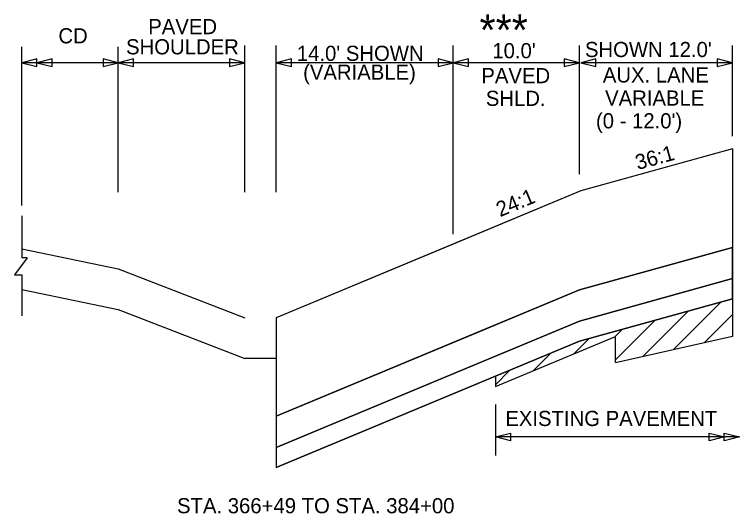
# Model space of a CAD drawing. Extents: x 4832 to 5477, y 4935 to 5220.
# Drawn here: x 4832.5 to 4889.8, y 5046 to 5085.4 of the extents above; entities that cross this region are included whole.
import ezdxf

# ---------------------------------------------------------------- set-up
doc = ezdxf.new("R2010")
doc.units = 0
for name, color, linetype in [('CLS_Clear_Zone', 7, 'Continuous'), ('Level 2', 7, 'Continuous'), ('RD_QTY_Milling', 7, 'Continuous'), ('RD_QTY_Miscl_1', 7, 'Continuous'), ('RD_QTY_Surf_Course', 7, 'Continuous'), ('RD_SHT_Typical', 7, 'Continuous'), ('RD_TX_TypSect', 7, 'Continuous'), ('RD_XS_ExPaveRet', 7, 'Continuous'), ('RD_XS_PaveShd', 7, 'Continuous'), ('TERMINATOR', 7, 'Continuous')]:
    doc.layers.add(name, color=color, linetype=linetype)

# ---------------------------------------------------------------- blocks, each defined once
blk = doc.blocks.new('AH')
at = {"layer": 'TERMINATOR'}
blk.add_lwpolyline([(-6, 1.5), (0, 0), (-6, -1.5)], close=True, dxfattribs=at)

msp = doc.modelspace()

# ---------------------------------------------------------------- linework, layer by layer
at = {"layer": 'CLS_Clear_Zone'}
msp.add_line((4853.19, 5053.657), (4853.19, 5049.59), dxfattribs=at)
at = {"layer": 'Level 2'}
msp.add_line((4853.188, 5058.235), (4850.689, 5058.235), dxfattribs=at)
at = {"layer": 'RD_QTY_Milling'}
for p, q in [((4889.27, 5067.011), (4889.27, 5067.011)), ((4889.27, 5067.011), (4889.27, 5067.011)), ((4889.27, 5064.542), (4889.27, 5067.011)), ((4853.19, 5053.657), (4853.19, 5051.188))]:
    msp.add_line(p, q, dxfattribs=at)
for points in [[(4889.27, 5067.011), (4877.179, 5063.653), (4853.19, 5053.657)], [(4853.19, 5051.188), (4877.179, 5061.183), (4889.27, 5064.542)]]:
    msp.add_lwpolyline(points, dxfattribs=at)
at = {"layer": 'RD_QTY_Miscl_1'}
for p, q in [((4889.27, 5064.542), (4877.179, 5061.183)), ((4889.275, 5062.946), (4889.27, 5064.542)), ((4889.27, 5064.542), (4889.27, 5064.542)), ((4877.179, 5059.586), (4889.275, 5062.946)), ((4877.179, 5059.586), (4877.179, 5059.586))]:
    msp.add_line(p, q, dxfattribs=at)
msp.add_lwpolyline([(4877.179, 5061.183), (4853.19, 5051.188), (4853.19, 5049.59), (4877.179, 5059.586)], dxfattribs=at)
at = {"layer": 'RD_QTY_Surf_Course'}
msp.add_line((4833.053, 5066.907), (4840.693, 5065.32), dxfattribs=at)
at = {"layer": 'RD_SHT_Typical'}
for p, q in [((4889.275, 5074.819), (4877.279, 5071.487)), ((4833.053, 5069.504), (4833.054, 5066.184)), ((4889.27, 5067.011), (4877.179, 5063.653)), ((4833.489, 5066.184), (4832.482, 5064.837)), ((4833.489, 5066.184), (4833.054, 5066.184)), ((4832.482, 5064.837), (4833.054, 5064.837)), ((4833.054, 5064.837), (4833.055, 5061.595)), ((4889.27, 5064.542), (4877.179, 5061.183)), ((4833.054, 5063.688), (4840.693, 5062.093)), ((4877.179, 5063.653), (4853.19, 5053.657)), ((4889.275, 5062.946), (4877.179, 5059.586)), ((4877.179, 5061.183), (4853.19, 5051.188)), ((4853.189, 5059.842), (4853.19, 5053.657)), ((4877.179, 5059.586), (4853.19, 5049.59))]:
    msp.add_line(p, q, dxfattribs=at)
at = {"layer": 'RD_TX_TypSect'}
for p, q in [((4833.053, 5070.33), (4833.053, 5082.89)), ((4840.693, 5071.39), (4840.693, 5082.89)), ((4850.689, 5071.39), (4850.689, 5083.004)), ((4853.188, 5071.39), (4853.188, 5083.004)), ((4867.183, 5068.065), (4867.183, 5083.004)), ((4877.179, 5072.801), (4877.179, 5083.004)), ((4889.27, 5075.82), (4889.27, 5083.004)), ((4840.693, 5081.63), (4833.053, 5081.63)), ((4850.689, 5081.63), (4840.693, 5081.63)), ((4867.183, 5081.631), (4853.188, 5081.63)), ((4877.166, 5081.631), (4867.183, 5081.631)), ((4889.27, 5081.631), (4877.274, 5081.631)), ((4889.275, 5074.819), (4877.279, 5071.487)), ((4889.275, 5074.819), (4889.27, 5067.011)), ((4889.275, 5074.819), (4889.275, 5074.819)), ((4877.279, 5071.487), (4853.188, 5061.449)), ((4877.179, 5063.653), (4889.27, 5067.011)), ((4889.27, 5067.011), (4889.27, 5067.011)), ((4853.188, 5061.449), (4853.188, 5061.449)), ((4853.188, 5061.449), (4853.19, 5053.657)), ((4870.524, 5054.583), (4870.524, 5050.555)), ((4853.19, 5053.657), (4853.19, 5053.657)), ((4889.827, 5052.012), (4870.524, 5052.012))]:
    msp.add_line(p, q, dxfattribs=at)
msp.add_lwpolyline([(4853.19, 5053.657), (4868.385, 5059.989), (4877.179, 5063.653)], dxfattribs=at)
at = {"layer": 'RD_XS_ExPaveRet'}
for p, q in [((4884.617, 5058.933), (4888.381, 5062.697)), ((4882.187, 5058.388), (4885.771, 5061.973)), ((4887.046, 5059.478), (4889.275, 5061.706)), ((4880.021, 5058.107), (4883.162, 5061.248)), ((4879.985, 5059.955), (4880.552, 5060.523)), ((4870.524, 5056.012), (4880.021, 5059.97)), ((4876.752, 5058.608), (4877.942, 5059.798)), ((4880.021, 5057.903), (4889.275, 5059.977)), ((4880.021, 5057.903), (4880.021, 5059.97)), ((4873.52, 5057.26), (4874.892, 5058.633)), ((4870.524, 5056.15), (4871.661, 5057.287)), ((4870.524, 5056.813), (4870.524, 5056.012))]:
    msp.add_line(p, q, dxfattribs=at)
at = {"layer": 'RD_XS_PaveShd'}
for p, q in [((4889.275, 5074.819), (4889.275, 5059.965)), ((4877.279, 5071.487), (4867.183, 5067.28)), ((4867.183, 5067.28), (4853.188, 5061.449)), ((4840.693, 5065.32), (4850.689, 5061.449)), ((4840.693, 5062.093), (4850.689, 5058.222)), ((4853.188, 5061.449), (4853.189, 5059.842))]:
    msp.add_line(p, q, dxfattribs=at)

# ---------------------------------------------------------------- block references
at = {"layer": 'TERMINATOR'}
for p, xscale, yscale, rotation in [((4833.053, 5081.63), 0.2000217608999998, -0.20002176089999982, -179.998582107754), ((4834.253, 5081.63), 0.2000217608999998, -0.20002176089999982, -179.998582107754), ((4840.693, 5081.63), 0.2000217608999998, -0.20002176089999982, 0.0014178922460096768), ((4840.693, 5081.63), 0.2000217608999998, -0.20002176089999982, -179.998582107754), ((4850.689, 5081.63), 0.2000217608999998, -0.20002176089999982, 0.0014178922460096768), ((4853.188, 5081.63), 0.2000217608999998, -0.20002176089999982, -179.998582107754), ((4867.183, 5081.631), 0.2000217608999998, -0.20002176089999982, 0.0014178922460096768), ((4867.183, 5081.631), 0.2000217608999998, -0.20002176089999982, -179.998582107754), ((4877.274, 5081.631), 0.20002176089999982, -0.20002176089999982, -179.99858211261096), ((4889.27, 5081.631), 0.20002176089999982, -0.20002176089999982, 0.0014178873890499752), ((4870.524, 5052.012), 0.1999217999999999, 0.1999217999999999, 180), ((4888.627, 5052.012), 0.2000217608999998, 0.20002176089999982, -0.0014178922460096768), ((4889.827, 5052.012), 0.2000217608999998, 0.20002176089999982, -0.0014178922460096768)]:
    msp.add_blockref('AH', p, dxfattribs=dict(at, xscale=xscale, yscale=yscale, rotation=rotation))
at = {"layer": 'TERMINATOR', "xscale": 0.2000217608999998, "yscale": -0.2000217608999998}
msp.add_blockref('AH', (4877.166, 5081.631), dxfattribs=at)

# ---------------------------------------------------------------- texts
at = {"layer": 'RD_TX_TypSect'}
for s, height, p in [('***', 2.4431, (4869.268, 5083.002)), ('PAVED', 1.2, (4843.062, 5083.887)), ('CD', 1.2, (4835.955, 5083.16)), ('SHOULDER', 1.2, (4841.305, 5082.29)), ("14.0' SHOWN", 1.2, (4854.815, 5081.772)), ('(VARIABLE)', 1.2, (4855.31, 5080.283)), ('VARIABLE', 1.2, (4879.196, 5078.234)), ("(0 - 12.0')", 1.2, (4878.474, 5076.434)), ('STA. 366+49 TO STA. 384+00', 1.2, (4845.338, 5045.973))]:
    msp.add_text(s, height=height, dxfattribs=at).set_placement(p)
for s, height, rotation, p in [("10.0'", 1.2, 359.99858, (4870.276, 5081.981)), ("SHOWN 12.0'", 1.2, 0.00071, (4877.603, 5082.075)), ('PAVED', 1.2, 359.99858, (4869.408, 5080.008)), ('AUX. LANE', 1.2, 359.99858, (4879.018, 5080.063)), ('SHLD.', 1.2, 359.99858, (4869.763, 5078.211)), ('36:1', 1.2, 15.52411, (4881.776, 5073.131)), ('24:1', 1.2, 22.61986, (4870.888, 5069.401)), ('EXISTING PAVEMENT', 1.20007, 360, (4871.303, 5052.879))]:
    msp.add_text(s, height=height, rotation=rotation, dxfattribs=at).set_placement(p)

doc.saveas('drawing.dxf')
